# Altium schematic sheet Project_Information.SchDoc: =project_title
size Tabloid; CompanyName: Luxonis Holding; Organization: Luxonis Holding; Address1: 1925 Harmony Park Drive; Address2: Westminster, CO; Address3: 80234; Address4: United States; SheetNumber: 1; SheetTotal: 3
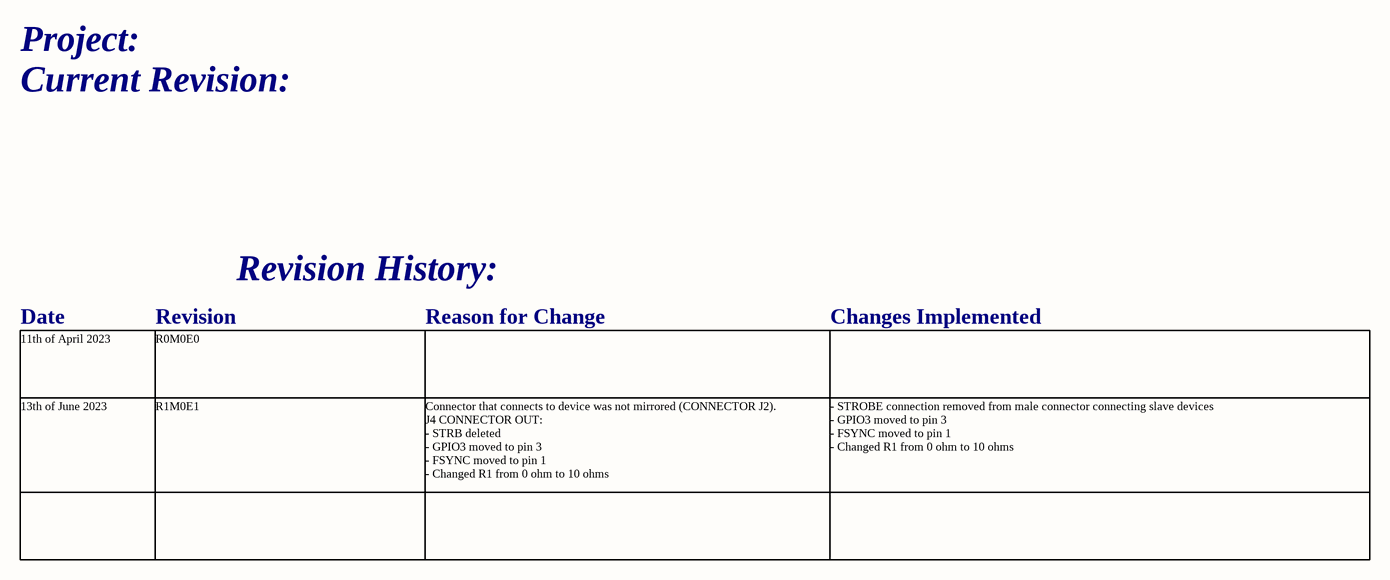
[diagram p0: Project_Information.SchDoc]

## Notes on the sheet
- Project:
- Current Revision:
- Revision History:
- Date
- Revision
- Reason for Change
- Changes Implemented
- 11th of April 2023
- R0M0E0
- 13th of June 2023
- R1M0E1
- Connector that connects to device was not mirrored (CONNECTOR J2).
  J4 CONNECTOR OUT:
  - STRB deleted
  - GPIO3 moved to pin 3
  - FSYNC moved to pin 1
  - Changed R1 from 0 ohm to 10 ohms
- - STROBE connection removed from male connector connecting slave devices
  - GPIO3 moved to pin 3
  - FSYNC moved to pin 1
  - Changed R1 from 0 ohm to 10 ohms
